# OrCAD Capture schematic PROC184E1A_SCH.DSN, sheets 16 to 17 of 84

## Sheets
16 16. SOC MCU FLASH: size C; title: SOC MCU FLASH; company: TEXAS INSTRUMENTS INCORPORATED; note: PROC184_SCH
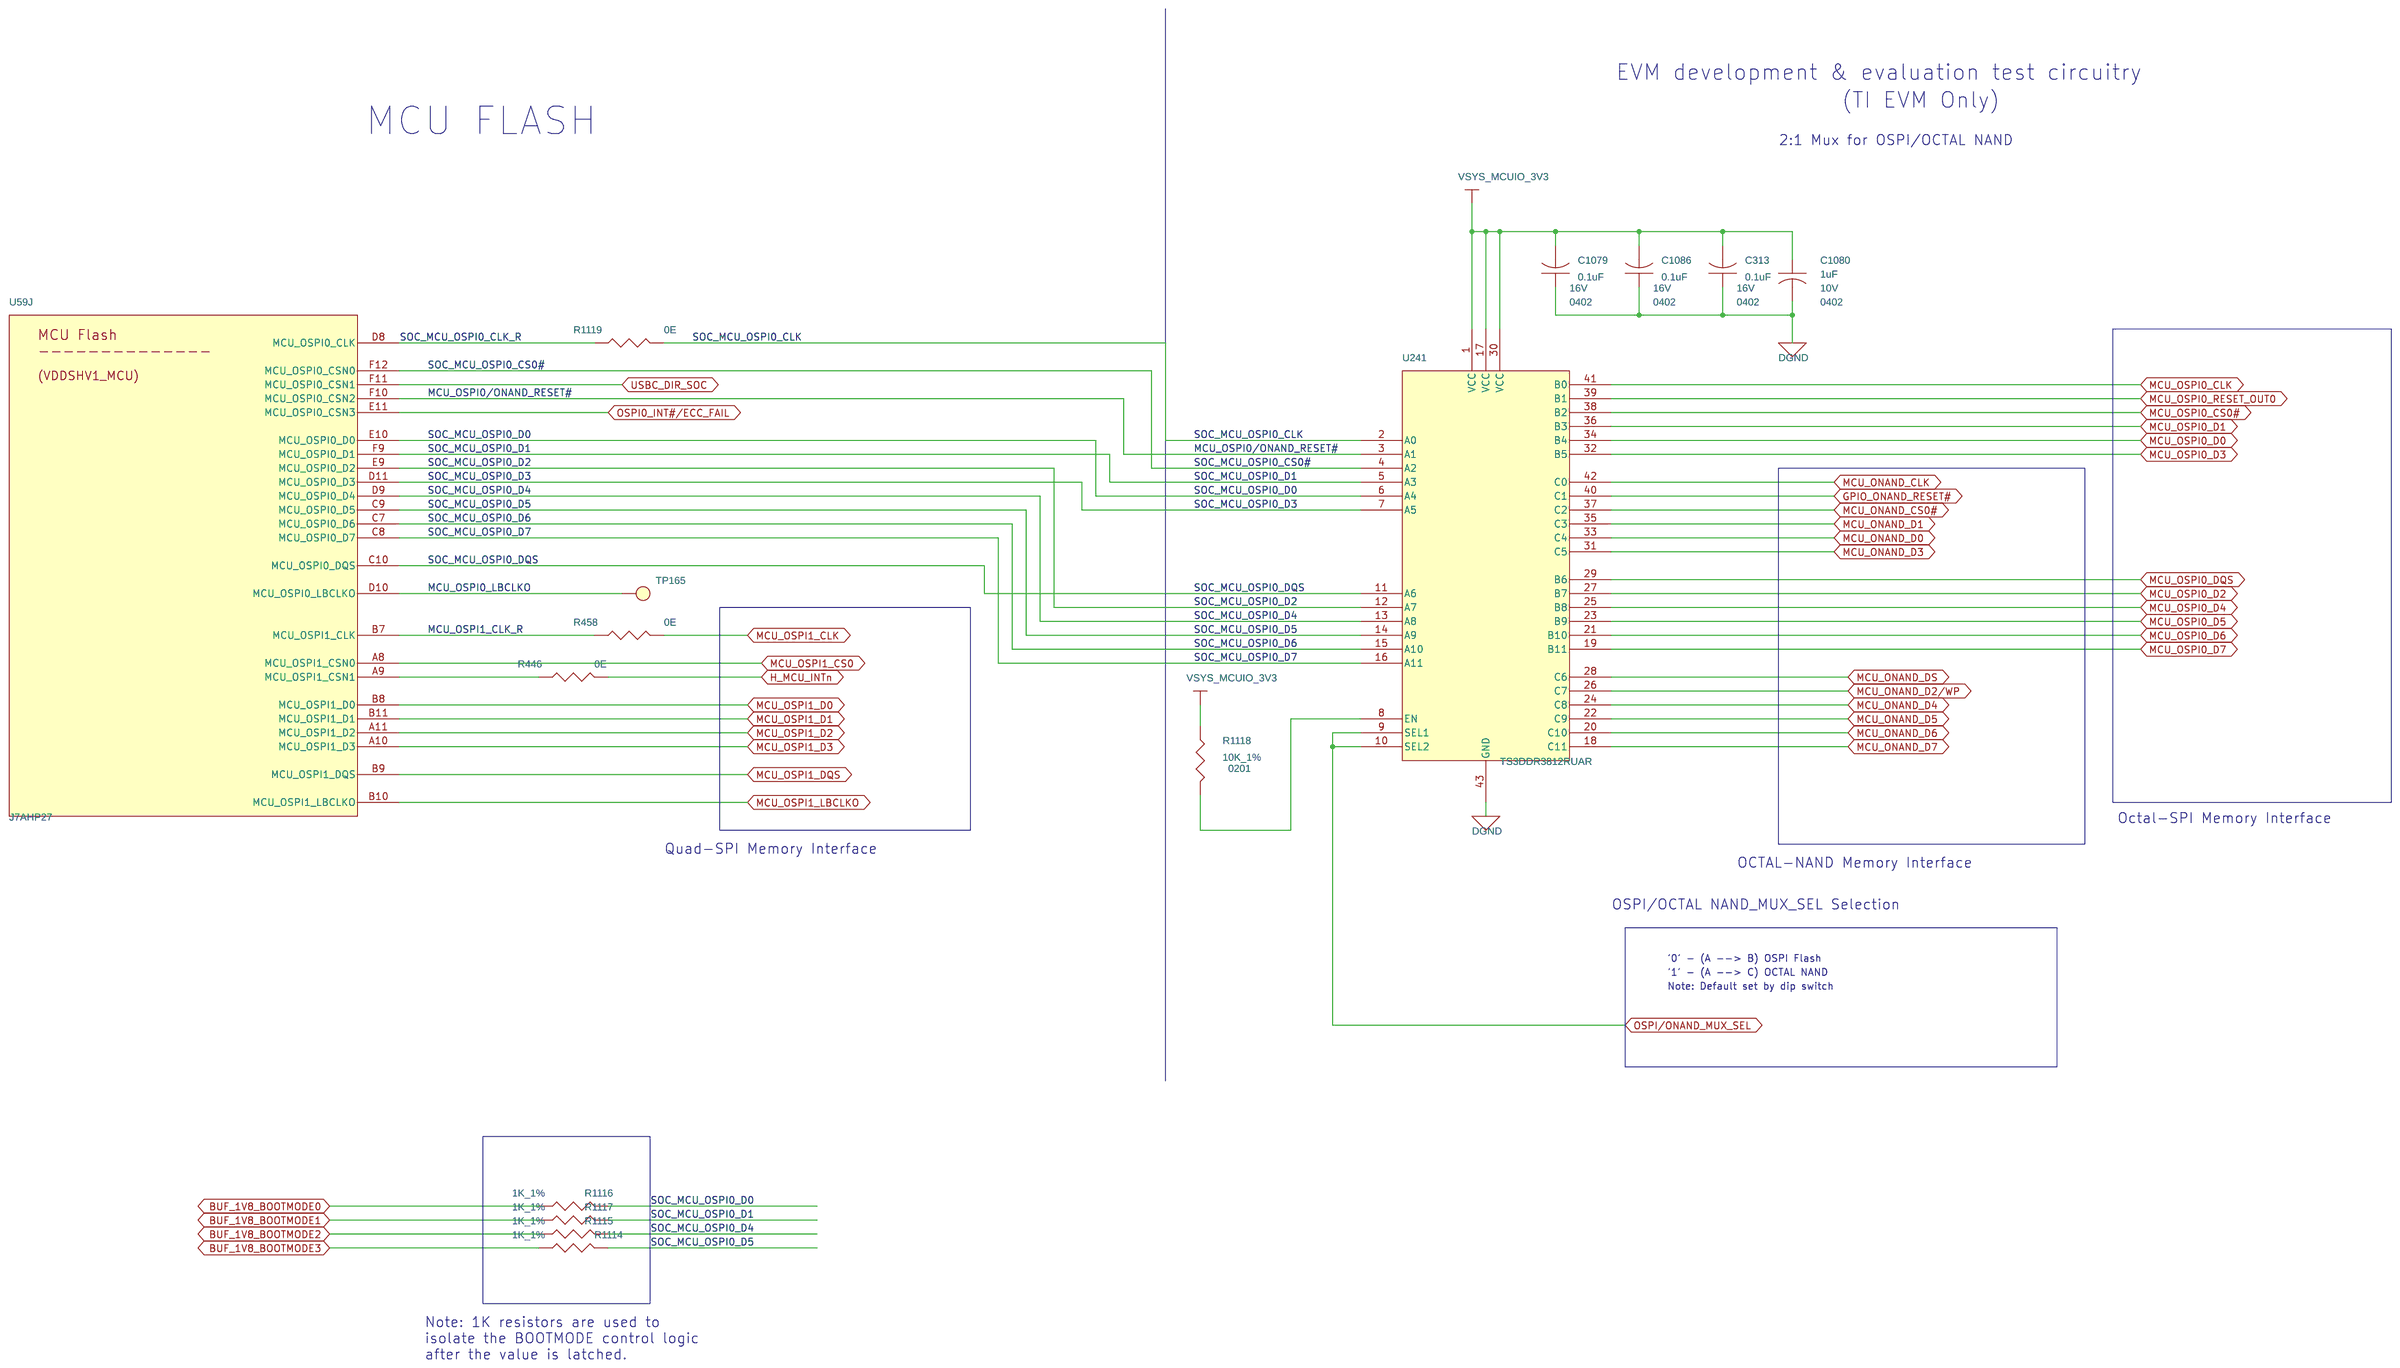
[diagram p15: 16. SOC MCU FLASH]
17 17. SoM FLASH OSPI & HYPER: size C; title: OSPIFLASH/HYPERFLAS/HYPERRAM; company: TEXAS INSTRUMENTS INCORPORATED; note: PROC184_SCH
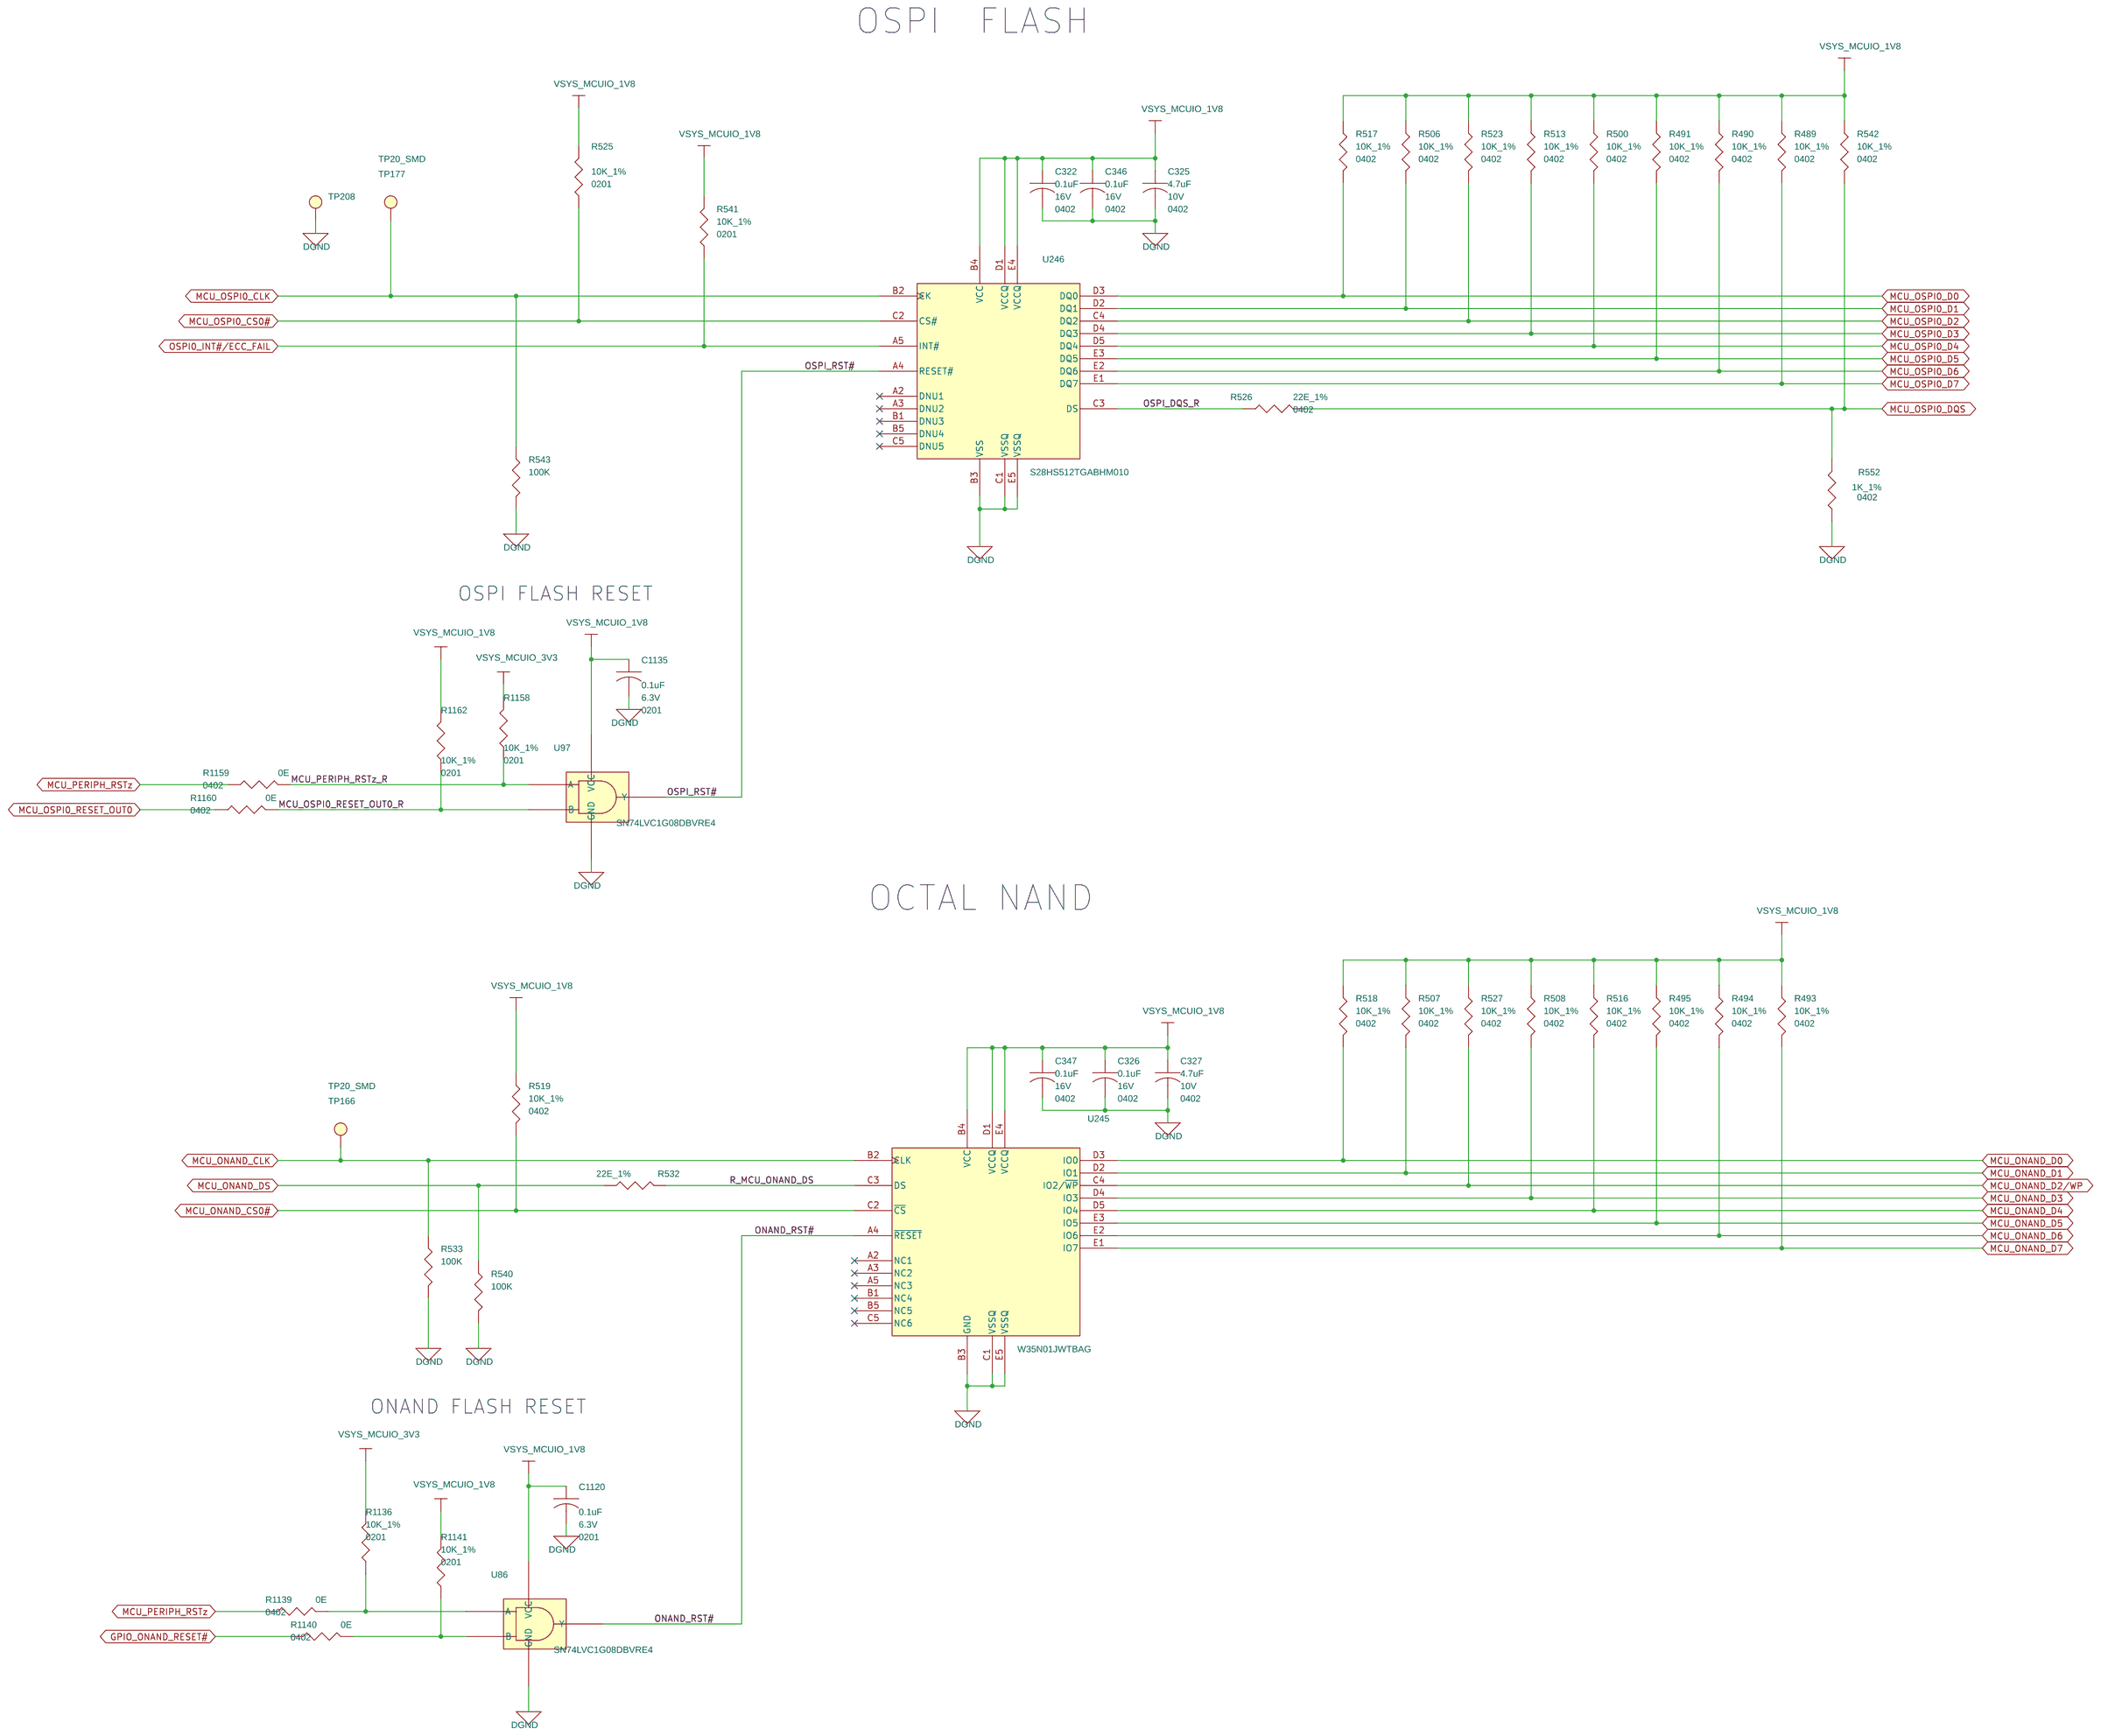
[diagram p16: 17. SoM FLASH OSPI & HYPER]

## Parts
sheet 15. SOC EMIF1 & LPDDR4
U59  J7AHP27  [BGASKT-33X33-1063-P8MM]  (sections A,B,C,D,E,F,G,H,I,J,K,L,M,N,O,P,Q,R,S,T,U,V,W)
sheet 16. SOC MCU FLASH
C313  0.1uF  [CAP0402_0-75]
C1079  0.1uF  [CAP0402_0-75]
C1080  1uF  [CAP0402_0-75]
C1086  0.1uF  [CAP0402_0-75]
R446  0E  [RES0402_0-5]
R458  0E  [RES0402_0-5]
R1114  1K_1%  [RES0201_0-5]
R1115  1K_1%  [RES0201_0-5]
R1116  1K_1%  [RES0201_0-5]
R1117  1K_1%  [RES0201_0-5]
R1118  10K_1%  [RES0201_0-5]
R1119  0E  [RES0402_0-5]
TP165  TP30_SMD  [TP30_SMD]
U241  TS3DDR3812RUAR  [TQFN42_19-68_140X360_0-8]
sheet 17. SoM FLASH OSPI & HYPER
C322  0.1uF  [CAP0402_0-75]
C325  4.7uF  [CAP0402_0-75]
C326  0.1uF  [CAP0402_0-75]
C327  4.7uF  [CAP0402_0-75]
C346  0.1uF  [CAP0402_0-75]
C347  0.1uF  [CAP0402_0-75]
C1120  0.1uF  [CAP0201_0-5]
C1135  0.1uF  [CAP0201_0-5]
R489  10K_1%  [RES0402_0-5]
R490  10K_1%  [RES0402_0-5]
R491  10K_1%  [RES0402_0-5]
R493  10K_1%  [RES0402_0-5]
R494  10K_1%  [RES0402_0-5]
R495  10K_1%  [RES0402_0-5]
R500  10K_1%  [RES0402_0-5]
R506  10K_1%  [RES0402_0-5]
R507  10K_1%  [RES0402_0-5]
R508  10K_1%  [RES0402_0-5]
R513  10K_1%  [RES0402_0-5]
R516  10K_1%  [RES0402_0-5]
R517  10K_1%  [RES0402_0-5]
R518  10K_1%  [RES0402_0-5]
R519  10K_1%  [RES0402_0-5]
R523  10K_1%  [RES0402_0-5]
R525  10K_1%  [RES0201_0-5]
R526  22E_1%  [RES0402_0-5]
R527  10K_1%  [RES0402_0-5]
R532  22E_1%  [RES0402_0-5]
R533  100K  [RES0402_0-5]
R540  100K  [RES0402_0-5]
R541  10K_1%  [RES0201_0-5]
R542  10K_1%  [RES0402_0-5]
R543  100K  [RES0402_0-5]
R552  1K_1%  [RES0402_0-5]
R1136  10K_1%  [RES0201_0-5]
R1139  0E  [RES0402_0-5]
R1140  0E  [RES0402_0-5]
R1141  10K_1%  [RES0201_0-5]
R1158  10K_1%  [RES0201_0-5]
R1159  0E  [RES0402_0-5]
R1160  0E  [RES0402_0-5]
R1162  10K_1%  [RES0201_0-5]
TP166  TP20_SMD  [TP20_SMD]
TP177  TP20_SMD  [TP20_SMD]
TP208  TP30_SMD  [TP30_SMD]
U86  SN74LVC1G08DBVRE4  [SOT23-5]
U97  SN74LVC1G08DBVRE4  [SOT23-5]
U245  W35N01JWTBAG  [TPBGA24_39-37_240X320_1-2]
U246  S28HS512TGABHM010  [BGA24_39-37_240X310_1]

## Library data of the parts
U59 = J7AHP27SoC_BGA1063: IC J7AHP27 SoC EVM MICROPROCESSOR BGA1063; Chkd/date: PRADEEP/181223; Crtd /date: TAMILARASU/111223; Custom_Duty: 15%; Customs_HS_Code: 85423100; Distributor_name: NA; Distributor_part_number: NA; Footprint Path: Y:\MIS_DATABASE\Library\ALTIUM_TOOL\PCB_FOOTPRINTS\Altium_Footprint_Lib.PcbLib; Height: 3.30MM; Library Path: Y:\MIS_DATABASE\Library\ALTIUM_TOOL\SCHEMATICS_PARTS\MS_MICROPROCESSOR_Library.schlib; Mfr_name: NA; Mistral Part No: 141223120002; Package: BGA1063; Part_type: ICS\DIGITAL\MICROPROCESSOR; Project: J7AHP27_V08 SOC; RoHS: NA; Temperature: NA; Tolerance: NA; Voltage: NA; Wattage: NA; Weight: NA; Datasheet: Y:\MIS_DATABASE\DATASHEETS\ICS\DIGITAL\MICROCONTROLLER\J7AHP27.PDF
C313 C322 C326 C346 C347 C1079 C1086 = CAP: CAP CERAMIC 0.1uF 16V 10% X7R AUTO 0402; Automotive Alternate_mfr_name: TDK; Automotive Alternate_mfr_part_number: CGA2B1X7R1C104K050BC; Chkd/date: NAVEED/021014; Crtd /date: VASANTHA/300514; Custom_Duty: 15%; Customs_HS_Code: 85322990; Direct Alternate_mfr_name: TDK; Direct Alternate_mfr_part_number: CGA2B1X7R1C104K050BC; Distributor_name: DIGIKEY; Distributor_part_number: 490-4759-1-ND; Footprint Path: Y:\MIS_DATABASE\Library\ALTIUM_TOOL\PCB_FOOTPRINTS\Altium_Footprint_Lib.PcbLib; Height: 0.55MM; Library Path: Y:\MIS_DATABASE\Library\ALTIUM_TOOL\SCHEMATICS_PARTS\MS_DISCRETE_Library.schlib; Manufacturer: MURATA; Mfr_name: MURATA; Mfr_part_number: GCM155R71C104KA55D; Mistral Part No: 120016070006-R; Package: 0402; Part_type: CAPACITORS\CERAMIC; Project: DCMIST_FPGA_CARD; RoHS: RoHS; Temperature: -55°C+125°C; Tolerance: 10%; Voltage: 16V; Wattage: NA; Weight: 6mg; Datasheet: Y:\MIS_DATABASE\DATASHEETS\CAPACITORS\MURATA-GCM-SER.PDF
C1080 = CAP: CAP CERAMIC 1uF 10V 10% X7S AUTO 0402; Chkd/date: MANIRAJA/100918; Crtd /date: ALVY/100918; Custom_Duty: 15%; Customs_HS_Code: 85322990; Distributor_name: DIGIKEY; Distributor_part_number: 490-13409-1-ND; Footprint Path: Y:\MIS_DATABASE\Library\ALTIUM_TOOL\PCB_FOOTPRINTS\Altium_Footprint_Lib.PcbLib; Height: 0.70MM; Library Path: Y:\MIS_DATABASE\Library\ALTIUM_TOOL\SCHEMATICS_PARTS\MS_DISCRETE_Library.schlib; Manufacturer: MURATA; Mfr_name: MURATA; Mfr_part_number: GCM155C71A105KE38D; Mistral Part No: 120018090021-R; Package: 0402; Part_type: CAPACITORS\CERAMIC; Project: SMART-M_SCRIPTALK_PB; RoHS: RoHS; Temperature: -55°C+125°C; Tolerance: 10%; Voltage: 10V; Wattage: NA; Weight: 6mg; Datasheet: Y:\MIS_DATABASE\DATASHEETS\CAPACITORS\MURATA-GCM-SER.PDF
R446 R458 R1119 R1139 R1159 = RESISTOR: RES 0E 1/10W JUMPER 0402; Chkd/date: VASANTHA/061216; Crtd /date: NAVEED/201014; Custom_Duty: 15%; Customs_HS_Code: 85332119; Distributor_name: DIGIKEY; Distributor_part_number: P0.0JCT-ND; Footprint Path: Y:\MIS_DATABASE\Library\ALTIUM_TOOL\PCB_FOOTPRINTS\Altium_Footprint_Lib.PcbLib; Height: 0.40MM; IBISSP_MODLES: VALUE REPEATING 2 TIME; Library Path: Y:\MIS_DATABASE\Library\ALTIUM_TOOL\SCHEMATICS_PARTS\MS_DISCRETE_Library.schlib; Manufacturer: PANASONIC-ECG; Mfr_name: PANASONIC-ECG; Mfr_part_number: ERJ-2GE0R00X; Mistral Part No: 110018030052-R; Package: 0402; Part_type: RESISTORS\FIXED; Project: AEGIS POM; RoHS: RoHS; Temperature: -55°C+155°C; Tolerance: NA; Voltage: NA; Wattage: 1/10W; Weight: 0.8mg; Datasheet: Y:\MIS_DATABASE\DATASHEETS\RESISTORS\PAN-ERJSER_NOV17.PDF
R1114-R1117 = RESISTOR: RES 1K 1/20W 1% 0201; Chkd/date: RAGESH/120511; Crtd /date: MAZHAR/100511; Custom_Duty: 15%; Customs_HS_Code: 85332119; Distributor_name: MOUSER; Distributor_part_number: 660-RK73H1HTTC1001F; Footprint Path: Y:\MIS_DATABASE\Library\ALTIUM_TOOL\PCB_FOOTPRINTS\Altium_Footprint_Lib.PcbLib; Height: 0.26MM; Library Path: Y:\MIS_DATABASE\Library\ALTIUM_TOOL\SCHEMATICS_PARTS\MS_DISCRETE_Library.schlib; Manufacturer: KOA SPEER; Mfr_name: KOA SPEER; Mfr_part_number: RK73H1HTTC1001F; Mistral Part No: 110015080014-R; Package: 0201; Part_type: RESISTORS\FIXED; Project: HMC; RoHS: RoHS; Temperature: -55°C+155°C; Tolerance: 1%; Voltage: NA; Wattage: 1/20W; Weight: 0.17mg; Datasheet: Y:\MIS_DATABASE\DATASHEETS\RESISTORS\RK73H-SER.PDF
R525 R541 R1118 R1136 R1141 R1158 R1162 = RESISTOR: RES 10K 1/20W 1% 0201; Chkd/date: MANIRAJA/080519; Crtd /date: ALVY/080519; Custom_Duty: 15%; Customs_HS_Code: 85332119; Distributor_name: DIGIKEY; Distributor_part_number: 1276-3670-1-ND; Footprint Path: Y:\MIS_DATABASE\Library\ALTIUM_TOOL\PCB_FOOTPRINTS\Altium_Footprint_Lib.PcbLib; Height: 0.26MM; Library Path: Y:\MIS_DATABASE\Library\ALTIUM_TOOL\SCHEMATICS_PARTS\MS_DISCRETE_Library.schlib; Manufacturer: SAMSUNG; Mfr_name: SAMSUNG; Mfr_part_number: RC0603F103CS; Mistral Part No: 110011040018-R; Package: 0201; Part_type: RESISTORS\FIXED; Project: BRUKER_SD820_COMMONDO; RoHS: RoHS; Temperature: -55°C+125°C; Tolerance: 1%; Voltage: NA; Wattage: 1/20W; Weight: 0.15mg; Datasheet: Y:\MIS_DATABASE\DATASHEETS\RESISTORS\SAMSUNG_RC-SER.PDF
TP165 = TESTPOINT: TESTPOINT CIR 30 SMD; Chkd/date: SHREESHAIL/171006; Crtd /date: MAZHAR/171006; Custom_Duty: NA; Customs_HS_Code: NA; Distributor_name: NA; Distributor_part_number: NA; Footprint Path: Y:\MIS_DATABASE\Library\ALTIUM_TOOL\PCB_FOOTPRINTS\Altium_Footprint_Lib.PcbLib; Height: NA; Library Path: Y:\MIS_DATABASE\Library\ALTIUM_TOOL\SCHEMATICS_PARTS\MS_DISCRETE_Library.schlib; MECHANICAL 3D STEP FILE: NA; Manufacturer: LOCAL; Mfr_name: LOCAL; Mistral Part No: 130009030930; Package: SMD; Part #: NO-POP; Project: BT MODULE_CSRBC04; RoHS: NA; Temperature: NA; Tolerance: NA; Voltage: NA; Wattage: NA; Weight: NA; Datasheet: NA
U241 = TS3DDR3812RUAR_WQFN42: IC 12-CH 1:2 MUX/DEMUX SWITCH FOR DDR3 APPLICATION WQFN42; Chkd/date: MANIRAJA/250918; Crtd /date: ALVY/250918; Custom_Duty: 15%; Customs_HS_Code: 85423100; Distributor_name: DIGIKEY; Distributor_part_number: 296-28307-1-ND; Footprint Path: Y:\MIS_DATABASE\Library\ALTIUM_TOOL\PCB_FOOTPRINTS\Altium_Footprint_Lib.PcbLib; Height: 0.80MM; Library Path: Y:\MIS_DATABASE\Library\ALTIUM_TOOL\SCHEMATICS_PARTS\MS_COMBINATIONAL_Library.schlib; Manufacturer: TEXAS INSTRUMENTS; Mfr_name: TEXAS INSTRUMENTS; Mistral Part No: 141018090023-R; Package: WQFN42; Part_type: ICS\DIGITAL\COMBINATIONAL; Project: TI_J7ES_EVM_CP; RoHS: RoHS; Temperature: -40°C+85°C; Tolerance: NA; Voltage: NA; Wattage: NA; Weight: 54.8mg; Datasheet: Y:\MIS_DATABASE\DATASHEETS\ICS\DIGITAL\COMBINATIONAL\TS3DDR3812.PDF
C325 C327 = CAP: CAP CERAMIC 4.7uF 10V 20% X5R 0402; Automotive Alternate_mfr_name: TAIYO YUDEN; Automotive Alternate_mfr_part_number: JMK105BBJ475MVHF; Chkd/date: VASANTHA/061216; Crtd /date: CHAITHANYA/070612; Custom_Duty: 15%; Customs_HS_Code: 85322990; Direct Alternate_mfr_name: TAIYO YUDEN; Direct Alternate_mfr_part_number: JMK105BBJ475MV-F; Distributor_name: DIGIKEY; Distributor_part_number: 445-8023-1-ND; Footprint Path: Y:\MIS_DATABASE\Library\ALTIUM_TOOL\PCB_FOOTPRINTS\Altium_Footprint_Lib.PcbLib; Height: 0.55MM; Library Path: Y:\MIS_DATABASE\Library\ALTIUM_TOOL\SCHEMATICS_PARTS\MS_DISCRETE_Library.schlib; Manufacturer: MURATA; Mfr_name: TDK CORPORATION; Mfr_part_number: C1005X5R1A475M; Mistral Part No: 120012060002-R; Package: 0402; Part_type: CAPACITORS\CERAMIC; Project: IRIS; RoHS: RoHS; Temperature: -55°C+85°C; Tolerance: 20%; Voltage: 10V; Wattage: NA; Weight: 0.65mg; Datasheet: Y:\MIS_DATABASE\DATASHEETS\CAPACITORS\TDK-C-SER_JUL17.PDF
C1120 C1135 = CAP: CAP CERAMIC 0.1uF 6.3V 10% X7S AUTO 0201; Chkd/date: MANIRAJA/011018; Crtd /date: MANIRAJA/011018; Custom_Duty: 15%; Customs_HS_Code: 85322990; Distributor_name: NA; Distributor_part_number: NA; Footprint Path: Y:\MIS_DATABASE\Library\ALTIUM_TOOL\PCB_FOOTPRINTS\Altium_Footprint_Lib.PcbLib; Height: 0.33MM; Library Path: Y:\MIS_DATABASE\Library\ALTIUM_TOOL\SCHEMATICS_PARTS\MS_DISCRETE_Library.schlib; Manufacturer: MURATA; Mfr_name: MURATA; Mfr_part_number: GCM033C70J104KE02D; Mistral Part No: 120018100001-R; Package: 0201; Part_type: CAPACITORS\CERAMIC; Project: TI_J7_SVB-DUT; RoHS: RoHS; Temperature: -55°C+125°C; Tolerance: 10%; Voltage: 6.3V; Wattage: NA; Weight: NA; Datasheet: Y:\MIS_DATABASE\DATASHEETS\CAPACITORS\MURATA-GCM-SER.PDF
R489-R491 R493-R495 R500 R506-R508 R513 R516-R519 R542 = RESISTOR: RES 10K 1/16W 1% 0402; Assembly_Instruction: DNI; Chkd/date: VASANTHA/201216; Crtd /date: GEETHA/290506; Custom_Duty: 15%; Customs_HS_Code: 85332119; Distributor_name: DIGIKEY; Distributor_part_number: 311-10.0KLRTR-ND; Footprint Path: Y:\MIS_DATABASE\Library\ALTIUM_TOOL\PCB_FOOTPRINTS\Altium_Footprint_Lib.PcbLib; Height: 0.40MM; Library Path: Y:\MIS_DATABASE\Library\ALTIUM_TOOL\SCHEMATICS_PARTS\MS_DISCRETE_Library.schlib; Manufacturer: YAGEO AMERICA; Mfr_name: YAGEO AMERICA; Mfr_part_number: RC0402FR-0710KL; Mistral Part No: 110015090015-R; Package: 0402; Part_type: RESISTORS\FIXED; Project: VOCERA; RoHS: RoHS; Temperature: -55°C+155°C; Tolerance: 1%; Voltage: NA; Wattage: 1/16W; Weight: 0.65mg; Datasheet: Y:\MIS_DATABASE\DATASHEETS\RESISTORS\RCXXXXL-SER_MAR18.PDF
R523 R527 = RESISTOR: RES 10K 1/16W 1% 0402; Chkd/date: VASANTHA/201216; Crtd /date: GEETHA/290506; Custom_Duty: 15%; Customs_HS_Code: 85332119; Distributor_name: DIGIKEY; Distributor_part_number: 311-10.0KLRTR-ND; Footprint Path: Y:\MIS_DATABASE\Library\ALTIUM_TOOL\PCB_FOOTPRINTS\Altium_Footprint_Lib.PcbLib; Height: 0.40MM; Library Path: Y:\MIS_DATABASE\Library\ALTIUM_TOOL\SCHEMATICS_PARTS\MS_DISCRETE_Library.schlib; Manufacturer: YAGEO AMERICA; Mfr_name: YAGEO AMERICA; Mfr_part_number: RC0402FR-0710KL; Mistral Part No: 110015090015-R; Package: 0402; Part_type: RESISTORS\FIXED; Project: VOCERA; RoHS: RoHS; Temperature: -55°C+155°C; Tolerance: 1%; Voltage: NA; Wattage: 1/16W; Weight: 0.65mg; Datasheet: Y:\MIS_DATABASE\DATASHEETS\RESISTORS\RCXXXXL-SER_MAR18.PDF
R526 R532 = RESISTOR: RES 22E 1/16W 1% 0402; Chkd/date: SUHAS/290910; Crtd /date: MAZHAR/090909; Cust_part_number: 4700-80047E; Custom_Duty: 15%; Customs_HS_Code: 85332119; Distributor_name: DIGIKEY; Distributor_part_number: 311-22.0LRCT-ND; Footprint Path: Y:\MIS_DATABASE\Library\ALTIUM_TOOL\PCB_FOOTPRINTS\Altium_Footprint_Lib.PcbLib; Height: 0.40MM; Library Path: Y:\MIS_DATABASE\Library\ALTIUM_TOOL\SCHEMATICS_PARTS\MS_DISCRETE_Library.schlib; Manufacturer: YAGEO AMERICA; Mfr_name: YAGEO AMERICA; Mfr_part_number: RC0402FR-0722RL; Mistral Part No: 110009090004-R; Package: 0402; Part_type: RESISTORS\FIXED; Project: VMEFMCD; RoHS: RoHS; Temperature: -55°C+155°C; Tolerance: 1%; Voltage: NA; Wattage: 1/16W; Weight: 0.65mg; Datasheet: Y:\MIS_DATABASE\DATASHEETS\RESISTORS\RCXXXXL-SER_MAR18.PDF
R533 R540 R543 = RESISTOR: RES 100K 1/10W 5% 0402; Chkd/date: VASANTHA/291216; Crtd /date: GEETHA/190406; Custom_Duty: 15%; Customs_HS_Code: 85332119; Distributor_name: DIGIKEY; Distributor_part_number: P100KJCT-ND; Footprint Path: Y:\MIS_DATABASE\Library\ALTIUM_TOOL\PCB_FOOTPRINTS\Altium_Footprint_Lib.PcbLib; Height: 0.40MM; Library Path: Y:\MIS_DATABASE\Library\ALTIUM_TOOL\SCHEMATICS_PARTS\MS_DISCRETE_Library.schlib; Manufacturer: PANASONIC-ECG; Mfr_name: PANASONIC-ECG; Mfr_part_number: ERJ-2GEJ104X; Mistral Part No: 110009030177-R; Package: 0402; Part_type: RESISTORS\FIXED; Project: RED EYE; RoHS: RoHS; Temperature: -55°C+155°C; Tolerance: 5%; Voltage: NA; Wattage: 1/10W; Weight: 0.8mg; Datasheet: Y:\MIS_DATABASE\DATASHEETS\RESISTORS\PAN-ERJSER_NOV17.PDF
R552 = RESISTOR: RES 1K 1/10W 1% 0402; Chkd/date: VASANTHA/281216; Crtd /date: MAZHAR/150506; Custom_Duty: 15%; Customs_HS_Code: 85332119; Distributor_name: DIGIKEY; Distributor_part_number: P1.00KLCT-ND; Footprint Path: Y:\MIS_DATABASE\Library\ALTIUM_TOOL\PCB_FOOTPRINTS\Altium_Footprint_Lib.PcbLib; Height: 0.40MM; Library Path: Y:\MIS_DATABASE\Library\ALTIUM_TOOL\SCHEMATICS_PARTS\MS_DISCRETE_Library.schlib; Manufacturer: PANASONIC-ECG; Mfr_name: PANASONIC-ECG; Mfr_part_number: ERJ-2RKF1001X; Mistral Part No: 110009030411-R; Package: 0402; Part_type: RESISTORS\FIXED; Project: VOCERA; RoHS: RoHS; Temperature: -55°C+155°C; Tolerance: 1%; Voltage: NA; Wattage: 1/10W; Weight: 0.8mg; Datasheet: Y:\MIS_DATABASE\DATASHEETS\RESISTORS\PAN-ERJSER_NOV17.PDF
R1140 R1160 = RESISTOR: RES 0E 1/10W JUMPER 0402; Assembly_Instruction: DNI; Chkd/date: VASANTHA/061216; Crtd /date: NAVEED/201014; Custom_Duty: 15%; Customs_HS_Code: 85332119; Distributor_name: DIGIKEY; Distributor_part_number: P0.0JCT-ND; Footprint Path: Y:\MIS_DATABASE\Library\ALTIUM_TOOL\PCB_FOOTPRINTS\Altium_Footprint_Lib.PcbLib; Height: 0.40MM; IBISSP_MODLES: VALUE REPEATING 2 TIME; Library Path: Y:\MIS_DATABASE\Library\ALTIUM_TOOL\SCHEMATICS_PARTS\MS_DISCRETE_Library.schlib; Manufacturer: PANASONIC-ECG; Mfr_name: PANASONIC-ECG; Mfr_part_number: ERJ-2GE0R00X; Mistral Part No: 110018030052-R; Package: 0402; Part_type: RESISTORS\FIXED; Project: AEGIS POM; RoHS: RoHS; Temperature: -55°C+155°C; Tolerance: NA; Voltage: NA; Wattage: 1/10W; Weight: 0.8mg; Datasheet: Y:\MIS_DATABASE\DATASHEETS\RESISTORS\PAN-ERJSER_NOV17.PDF
TP166 TP177 = TESTPOINT: TESTPOINT CIR 20 SMD; Chkd/date: SHREESHAIL/171006; Crtd /date: MAZHAR/171006; Custom_Duty: NA; Customs_HS_Code: NA; Distributor_name: NA; Distributor_part_number: NA; Footprint Path: Y:\MIS_DATABASE\Library\ALTIUM_TOOL\PCB_FOOTPRINTS\Altium_Footprint_Lib.PcbLib; Height: NA; Library Path: Y:\MIS_DATABASE\Library\ALTIUM_TOOL\SCHEMATICS_PARTS\MS_DISCRETE_Library.schlib; MECHANICAL 3D STEP FILE: NA; Manufacturer: LOCAL; Mfr_name: LOCAL; Mistral Part No: NA; Package: SMD; Project: BT MODULE_CSRBC04; RoHS: NA; Temperature: NA; Tolerance: NA; Voltage: NA; Wattage: NA; Weight: NA; Datasheet: NA
TP208 = TESTPOINT: TESTPOINT CIR 30 SMD; Chkd/date: SHREESHAIL/171006; Crtd /date: MAZHAR/171006; Custom_Duty: NA; Customs_HS_Code: NA; Distributor_name: NA; Distributor_part_number: NA; Footprint Path: Y:\MIS_DATABASE\Library\ALTIUM_TOOL\PCB_FOOTPRINTS\Altium_Footprint_Lib.PcbLib; Height: NA; Library Path: Y:\MIS_DATABASE\Library\ALTIUM_TOOL\SCHEMATICS_PARTS\MS_DISCRETE_Library.schlib; MECHANICAL 3D STEP FILE: NA; Manufacturer: LOCAL; Mfr_name: LOCAL; Mistral Part No: 130009030930; Package: SMD; Project: BT MODULE_CSRBC04; RoHS: NA; Temperature: NA; Tolerance: NA; Voltage: NA; Wattage: NA; Weight: NA; Datasheet: NA
U86 U97 = SN74LVC1G08DBVRE4_SOT23-5: IC SINGLE 2-INPUT POSITIVE AND GATE SOT23-5; Automotive Alternate_mfr_name: TEXAS INSTRUMENTS; Automotive Alternate_mfr_part_number: SN74LVC1G08QDBVRQ1; Chkd/date: SUHAS/221010; Crtd /date: USMAN/151008; Custom_Duty: 15%; Customs_HS_Code: 85423100; Distributor_name: DIGIKEY; Distributor_part_number: SN74LVC1G08DBVRE4-ND; Height: 1.45MM; Manufacturer: TEXAS INSTRUMENTS; Mfr_name: TEXAS INSTRUMENTS; Mistral Part No: 141009060026-R; Part_type: ICS\DIGITAL\GATES; Project: KHAN_MAIN; RoHS: Sb/ Br FREE; Temperature: -40°C+85°C; Datasheet: Y:\MIS_DATABASE\DATASHEETS\ICS\DIGITAL\GATES\SN74LVC1G08.PDF
U245 = W35N01JWTB_TFBGA24: IC 1.7-1.95V 1Gb SERIAL SLC NAND FLASH MEMORY OCTAL SPI TFBGA24; Chkd/date: MANIRAJA/090421; Crtd /date: ALVY/080421; Custom_Duty: 15%; Customs_HS_Code: 85423100; Distributor_name: NA; Distributor_part_number: NA; Footprint Path: Y:\MIS_DATABASE\Library\ALTIUM_TOOL\PCB_FOOTPRINTS\Altium_Footprint_Lib.PcbLib; Height: 1.20MM; Library Path: Y:\MIS_DATABASE\Library\ALTIUM_TOOL\SCHEMATICS_PARTS\MS_MISCMEMORY_Library.schlib; Manufacturer: WINBOND; Mfr_name: WINBOND; Mistral Part No: 141121040002-R; Package: TFBGA24; Part_type: ICS\DIGITAL\MEMORY; Project: TI_J7AEP SOM BRD; RoHS: RoHS; Temperature: -40°C+105°C; Tolerance: NA; Voltage: NA; Wattage: NA; Weight: NA; Datasheet: Y:\MIS_DATABASE\DATASHEETS\ICS\MEMORY\W35N01JWXX.PDF
U246 = S28HS512T_BGA24: IC 1.8V 512Mb SEMPER FLASH WITH OCTAL INTERFACE BGA24; Chkd/date: MANIRAJA/170120; Crtd /date: ALVY/170120; Custom_Duty: 15%; Customs_HS_Code: 85423100; Distributor_name: NA; Distributor_part_number: NA; Footprint Path: Y:\MIS_DATABASE\Library\ALTIUM_TOOL\PCB_FOOTPRINTS\Altium_Footprint_Lib.PcbLib; Height: 1.00MM; Library Path: Y:\MIS_DATABASE\Library\ALTIUM_TOOL\SCHEMATICS_PARTS\MS_MISCMEMORY_Library.schlib; Manufacturer: CYPRESS SEMICONDUCTOR; Mfr_name: CYPRESS SEMICONDUCTOR; Mistral Part No: 141120010002; Package: BGA24; Part_type: ICS\DIGITAL\MEMORY; Project: J7VCL_SOM DUAL LEO PMIC; RoHS: NA; Temperature: -40°C+125°C; Tolerance: NA; Voltage: NA; Wattage: NA; Weight: NA; Datasheet: Y:\MIS_DATABASE\DATASHEETS\ICS\MEMORY\S28HS512T.PDF

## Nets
DGND: C313.1 C322.2 C325.2 C326.2 C327.2 C346.2 C347.2 C1079.1 C1080.2 C1086.1 C1120.2 C1135.2 R533.2 R540.2 R543.2 R552.1 TP208.1(TP) U86.3(GND) U97.3(GND) U241.43(GND) U245.B3(GND) U245.C1(VSSQ) U245.E5(VSSQ) U246.B3(VSS) U246.C1(VSSQ) U246.E5(VSSQ) ; also on sheet 11 12 13 14 15 18 20 21 22 23 24 25 26 27 28 29 30 31 32 33 34 35 36 37 38 39 40 41 42 43 44 45 46 47 48 49 50 51 52 53 54 55 56 57 58 59 60 61 62 63 64 65 66 67 68 69 70 71 72 73 76 77 78 79 81 82 83 84
BUF_1V8_BOOTMODE0: R1116.2 ; also on sheet 62
BUF_1V8_BOOTMODE1: R1117.2 ; also on sheet 62
BUF_1V8_BOOTMODE2: R1115.2 ; also on sheet 62
BUF_1V8_BOOTMODE3: R1114.2 ; also on sheet 62
GPIO_ONAND_RESET#: R1140.1 U241.40(C1)
H_MCU_INTn: R446.2 ; also on sheet 69
MCU_ONAND_CLK: R533.1 TP166.1(TP) U241.42(C0) U245.B2(CLK)
MCU_ONAND_CS0#: R519.2 U241.37(C2) U245.C2(~{CS})
MCU_ONAND_D0: R518.2 U241.33(C4) U245.D3(IO0)
MCU_ONAND_D1: R507.2 U241.35(C3) U245.D2(IO1)
MCU_ONAND_D2/WP: R527.2 U241.26(C7) U245.C4(IO2/~{WP})
MCU_ONAND_D3: R508.2 U241.31(C5) U245.D4(IO3)
MCU_ONAND_D4: R516.2 U241.24(C8) U245.D5(IO4)
MCU_ONAND_D5: R495.2 U241.22(C9) U245.E3(IO5)
MCU_ONAND_D6: R494.2 U241.20(C10) U245.E2(IO6)
MCU_ONAND_D7: R493.2 U241.18(C11) U245.E1(IO7)
MCU_ONAND_DS: R532.2 R540.1 U241.28(C6)
MCU_OSPI0/ONAND_RESET#: U59.F10(MCU_OSPI0_CSN2) U241.3(A1)
MCU_OSPI0_CLK: R543.1 TP177.1(TP) U241.41(B0) U246.B2(CK)
MCU_OSPI0_CS0#: R525.1 U241.38(B2) U246.C2(CS#)
MCU_OSPI0_D0: R517.2 U241.34(B4) U246.D3(DQ0)
MCU_OSPI0_D1: R506.2 U241.36(B3) U246.D2(DQ1)
MCU_OSPI0_D2: R523.2 U241.27(B7) U246.C4(DQ2)
MCU_OSPI0_D3: R513.2 U241.32(B5) U246.D4(DQ3)
MCU_OSPI0_D4: R500.2 U241.25(B8) U246.D5(DQ4)
MCU_OSPI0_D5: R491.2 U241.23(B9) U246.E3(DQ5)
MCU_OSPI0_D6: R490.2 U241.21(B10) U246.E2(DQ6)
MCU_OSPI0_D7: R489.2 U241.19(B11) U246.E1(DQ7)
MCU_OSPI0_DQS: R526.2 R542.2 R552.2 U241.29(B6)
MCU_OSPI0_LBCLKO: TP165.1(TP) U59.D10(MCU_OSPI0_LBCLKO)
MCU_OSPI0_RESET_OUT0: R1160.1 U241.39(B1)
MCU_OSPI0_RESET_OUT0_R: R1160.2 R1162.1 U97.2(B)
MCU_OSPI1_CLK: R458.2 ; also on sheet 39
MCU_OSPI1_CLK_R: R458.1 U59.B7(MCU_OSPI1_CLK)
MCU_OSPI1_CS0: U59.A8(MCU_OSPI1_CSN0) ; also on sheet 39
MCU_OSPI1_D0: U59.B8(MCU_OSPI1_D0) ; also on sheet 39
MCU_OSPI1_D1: U59.B11(MCU_OSPI1_D1) ; also on sheet 39
MCU_OSPI1_D2: U59.A11(MCU_OSPI1_D2) ; also on sheet 39
MCU_OSPI1_D3: U59.A10(MCU_OSPI1_D3) ; also on sheet 39
MCU_OSPI1_DQS: U59.B9(MCU_OSPI1_DQS) ; also on sheet 39
MCU_OSPI1_LBCLKO: U59.B10(MCU_OSPI1_LBCLKO) ; also on sheet 39
MCU_PERIPH_RSTz: R1139.1 R1159.1 ; also on sheet 18 37 44 62
MCU_PERIPH_RSTz_R: R1158.1 R1159.2 U97.1(A)
ONAND_RST#: U86.4(Y) U245.A4(~{RESET})
OSPI0_INT#/ECC_FAIL: R541.1 U59.E11(MCU_OSPI0_CSN3) U246.A5(INT#)
OSPI/ONAND_MUX_SEL: U241.9(SEL1) U241.10(SEL2) ; also on sheet 18 35
OSPI_DQS_R: R526.1 U246.C3(DS)
OSPI_RST#: U97.4(Y) U246.A4(RESET#)
R_MCU_ONAND_DS: R532.1 U245.C3(DS)
SOC_MCU_OSPI0_CLK: R1119.2 U241.2(A0)
SOC_MCU_OSPI0_CLK_R: R1119.1 U59.D8(MCU_OSPI0_CLK)
SOC_MCU_OSPI0_CS0#: U59.F12(MCU_OSPI0_CSN0) U241.4(A2)
SOC_MCU_OSPI0_D0: R1116.1 U59.E10(MCU_OSPI0_D0) U241.6(A4)
SOC_MCU_OSPI0_D1: R1117.1 U59.F9(MCU_OSPI0_D1) U241.5(A3)
SOC_MCU_OSPI0_D2: U59.E9(MCU_OSPI0_D2) U241.12(A7)
SOC_MCU_OSPI0_D3: U59.D11(MCU_OSPI0_D3) U241.7(A5)
SOC_MCU_OSPI0_D4: R1115.1 U59.D9(MCU_OSPI0_D4) U241.13(A8)
SOC_MCU_OSPI0_D5: R1114.1 U59.C9(MCU_OSPI0_D5) U241.14(A9)
SOC_MCU_OSPI0_D6: U59.C7(MCU_OSPI0_D6) U241.15(A10)
SOC_MCU_OSPI0_D7: U59.C8(MCU_OSPI0_D7) U241.16(A11)
SOC_MCU_OSPI0_DQS: U59.C10(MCU_OSPI0_DQS) U241.11(A6)
USBC_DIR_SOC: U59.F11(MCU_OSPI0_CSN1) ; also on sheet 53
VSYS_MCUIO_1V8: C322.1 C325.1 C326.1 C327.1 C346.1 C347.1 C1120.1 C1135.1 R489.1 R490.1 R491.1 R493.1 R494.1 R495.1 R500.1 R506.1 R507.1 R508.1 R513.1 R516.1 R517.1 R518.1 R519.1 R523.1 R525.2 R527.1 R541.2 R542.1 R1141.2 R1162.2 U86.5(VCC) U97.5(VCC) U245.B4(VCC) U245.D1(VCCQ) U245.E4(VCCQ) U246.B4(VCC) U246.D1(VCCQ) U246.E4(VCCQ) ; also on sheet 21 37 39 53 62 65 75
VSYS_MCUIO_3V3: C313.2 C1079.2 C1080.1 C1086.2 R1118.1 R1136.2 R1158.2 U241.1(VCC) U241.17(VCC) U241.30(VCC) ; also on sheet 18 21 22 23 35 36 43 44 48 49 55 62 65 68 75
N24594316: R1118.2 U241.8(EN)
N33174192: R1136.1 R1139.2 U86.1(A)
N33174210: R1140.2 R1141.1 U86.2(B)
N33175937: R446.1 U59.A9(MCU_OSPI1_CSN1)

Not connected (* = marked no-connect by the designer): U245 A2(NC1)* A3(NC2)* A5(NC3)* B1(NC4)* B5(NC5)* C5(NC6)*; U246 A2(DNU1)* A3(DNU2)* B1(DNU3)* B5(DNU4)* C5(DNU5)*

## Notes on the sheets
sheet 16
- EVM development & evaluation test circuitry
- (TI EVM Only)
- MCU FLASH
- 2:1 Mux for OSPI/OCTAL NAND
- Octal-SPI Memory Interface
- Quad-SPI Memory Interface
- OCTAL-NAND Memory Interface
- OSPI/OCTAL NAND_MUX_SEL Selection
- '0' - (A --> B) OSPI Flash
- '1' - (A --> C) OCTAL NAND
- Note: Default set by dip switch
- Note: 1K resistors are used to
  isolate the BOOTMODE control logic
  after the value is latched.
sheet 17
- OSPI  FLASH
- OSPI FLASH RESET
- OCTAL NAND
- ONAND FLASH RESET
